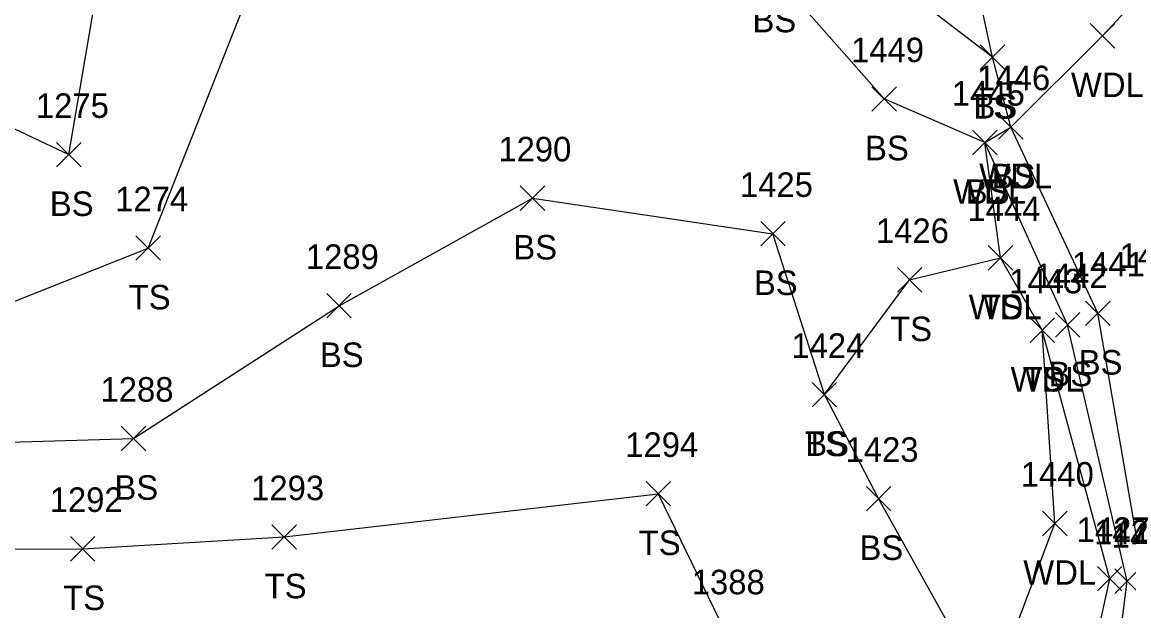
# Model space of a CAD drawing. Extents: x 1600281 to 1602254, y 862855 to 863227.
# Drawn here: x 1601927.2 to 1602017.5, y 862978.2 to 863026.2 of the extents above; entities that cross this region are included whole.
import ezdxf

# ---------------------------------------------------------------- set-up
doc = ezdxf.new("R2010")
doc.units = 0
for name, color, linetype in [('L_A', 7, 'Continuous'), ('L_I', 7, 'Continuous'), ('L_TIC', 7, 'Continuous'), ('LAWA', 7, 'Continuous'), ('LELB', 7, 'Continuous')]:
    doc.layers.add(name, color=color, linetype=linetype)

msp = doc.modelspace()

# ---------------------------------------------------------------- linework, layer by layer
at = {"layer": 'L_TIC'}
for points in [[(1602014.328, 863024.061), (1602016.328, 863026.061)], [(1602016.328, 863024.061), (1602014.328, 863026.061)], [(1602005.36, 863022.315), (1602007.36, 863024.315)], [(1602007.36, 863022.315), (1602005.36, 863024.315)], [(1602005.36, 863022.315), (1602007.36, 863024.315)], [(1602007.36, 863022.315), (1602005.36, 863024.315)], [(1601996.522, 863018.91), (1601998.522, 863020.91)], [(1601998.522, 863018.91), (1601996.522, 863020.91)], [(1602006.852, 863016.624), (1602008.852, 863018.624)], [(1602008.852, 863016.624), (1602006.852, 863018.624)], [(1602006.852, 863016.624), (1602008.852, 863018.624)], [(1602008.852, 863016.624), (1602006.852, 863018.624)], [(1602004.728, 863015.362), (1602006.728, 863017.362)], [(1602006.728, 863015.362), (1602004.728, 863017.362)], [(1602004.728, 863015.362), (1602006.728, 863017.362)], [(1602006.728, 863015.362), (1602004.728, 863017.362)], [(1601930.055, 863014.369), (1601932.055, 863016.369)], [(1601932.055, 863014.369), (1601930.055, 863016.369)], [(1601967.846, 863010.822), (1601969.846, 863012.822)], [(1601969.846, 863010.822), (1601967.846, 863012.822)], [(1601987.456, 863007.925), (1601989.456, 863009.925)], [(1601989.456, 863007.925), (1601987.456, 863009.925)], [(1601987.456, 863007.925), (1601989.456, 863009.925)], [(1601989.456, 863007.925), (1601987.456, 863009.925)], [(1601936.517, 863006.754), (1601938.517, 863008.754)], [(1601938.517, 863006.754), (1601936.517, 863008.754)], [(1602006, 863005.956), (1602008, 863007.956)], [(1602008, 863005.956), (1602006, 863007.956)], [(1602006, 863005.956), (1602008, 863007.956)], [(1602008, 863005.956), (1602006, 863007.956)], [(1601998.597, 863004.166), (1602000.597, 863006.166)], [(1602000.597, 863004.166), (1601998.597, 863006.166)], [(1601952.074, 863002.055), (1601954.074, 863004.055)], [(1601954.074, 863002.055), (1601952.074, 863004.055)], [(1602013.943, 863001.438), (1602015.943, 863003.438)], [(1602015.943, 863001.438), (1602013.943, 863003.438)], [(1602009.41, 863000.058), (1602011.41, 863002.058)], [(1602011.41, 863000.058), (1602009.41, 863002.058)], [(1602009.41, 863000.058), (1602011.41, 863002.058)], [(1602011.41, 863000.058), (1602009.41, 863002.058)], [(1602011.478, 863000.488), (1602013.478, 863002.488)], [(1602013.478, 863000.488), (1602011.478, 863002.488)], [(1601991.646, 862994.803), (1601993.646, 862996.803)], [(1601993.646, 862994.803), (1601991.646, 862996.803)], [(1601991.646, 862994.803), (1601993.646, 862996.803)], [(1601993.646, 862994.803), (1601991.646, 862996.803)], [(1601935.325, 862991.231), (1601937.325, 862993.231)], [(1601937.325, 862991.231), (1601935.325, 862993.231)], [(1601978.103, 862986.727), (1601980.103, 862988.727)], [(1601980.103, 862986.727), (1601978.103, 862988.727)], [(1601996.067, 862986.325), (1601998.067, 862988.325)], [(1601998.067, 862986.325), (1601996.067, 862988.325)], [(1602010.441, 862984.305), (1602012.441, 862986.305)], [(1602012.441, 862984.305), (1602010.441, 862986.305)], [(1601947.603, 862983.199), (1601949.603, 862985.199)], [(1601949.603, 862983.199), (1601947.603, 862985.199)], [(1601931.18, 862982.24), (1601933.18, 862984.24)], [(1601933.18, 862982.24), (1601931.18, 862984.24)], [(1602014.906, 862979.796), (1602016.906, 862981.796)], [(1602016.906, 862979.796), (1602014.906, 862981.796)], [(1602016.327, 862979.602), (1602018.327, 862981.602)], [(1602018.327, 862979.602), (1602016.327, 862981.602)]]:
    msp.add_lwpolyline(points, dxfattribs=at)
at = {"layer": 'LAWA'}
msp.add_lwpolyline([(1601918.484, 862969.325), (1601939.42, 862962.53), (1601955.985, 862947.407), (1601971.758, 862937.876), (1601975.725, 862943.556), (1601990.974, 862965.699), (1602006.102, 862971.122), (1602011.441, 862985.305), (1602010.41, 863001.058), (1602007, 863006.956), (1602005.728, 863016.362), (1602007.852, 863017.624), (1602015.328, 863025.061), (1602020.118, 863030.26)], dxfattribs=at)
at = {"layer": 'LELB'}
for points in [[(1601889.548, 862979.701), (1601879.53, 862980.196), (1601869.363, 862989.31), (1601873.745, 863000.271), (1601884.058, 863016.502), (1601890.014, 863028.231), (1601890.388, 863044.156), (1601893.555, 863052.296), (1601898.678, 863064.416), (1601898.005, 863054.108), (1601899.316, 863041.878), (1601901.962, 863029.12), (1601931.055, 863015.369), (1601935.902, 863043.881), (1601936.523, 863051.716)], [(1602006.36, 863023.315), (1601992.353, 863034.019), (1601989.377, 863048.159), (1601987.871, 863058.21)], [(1601850.487, 862982.969), (1601860.819, 862978.517), (1601879.357, 862968.779), (1601889.404, 862966.06), (1601913.787, 862945.707), (1601936.178, 862934.785), (1601958.999, 862928.536), (1601973.106, 862927.744), (1601983.044, 862929.485), (1601994.912, 862935.464), (1602008.175, 862945.227), (1602016.316, 862961.337), (1602018.761, 862980.317), (1602014.943, 863002.438), (1602007.852, 863017.624), (1602006.36, 863023.315), (1602003.161, 863037.99), (1602002.758, 863044.77), (1602006.602, 863051.128), (1602010.649, 863053.195)], [(1601881.596, 863023.768), (1601884.862, 863033.619), (1601890.388, 863044.156), (1601893.063, 863038.692), (1601893.536, 863030.212), (1601909.571, 863016.62), (1601907.502, 863002.961), (1601921.846, 863001.516), (1601937.517, 863007.754), (1601947.495, 863033.023)], [(1601958.999, 862928.536), (1601972.89, 862929.468), (1601981.162, 862933.435), (1601993.258, 862937.414), (1602005.114, 862948.359), (1602014.99, 862961.982), (1602017.327, 862980.602), (1602012.478, 863001.488), (1602005.728, 863016.362), (1601997.522, 863019.91), (1601988.341, 863030.346), (1601976.19, 863036.164)], [(1601913.251, 862991.536), (1601936.325, 862992.231), (1601953.074, 863003.055), (1601968.846, 863011.822), (1601988.456, 863008.925)], [(1602006.102, 862971.122), (1601997.067, 862987.325), (1601992.646, 862995.803), (1601988.456, 863008.925)], [(1601992.646, 862995.803), (1601999.597, 863005.166), (1602007, 863006.956)], [(1601991.981, 862939.355), (1602001.74, 862950.45), (1602012.079, 862963.37), (1602015.906, 862980.796), (1602010.41, 863001.058)], [(1601907.639, 862983.211), (1601932.18, 862983.24), (1601948.603, 862984.199), (1601979.103, 862987.727), (1601984.528, 862976.525), (1601990.974, 862965.699)]]:
    msp.add_lwpolyline(points, dxfattribs=at)

# ---------------------------------------------------------------- texts
at = {"layer": 'L_A'}
for s, p in [('BS', (1601986.782, 863025.346)), ('WDL', (1602012.745, 863020.061)), ('TS', (1602004.769, 863018.315)), ('BS', (1602004.801, 863018.315)), ('BS', (1601995.963, 863014.91)), ('WDL', (1602005.269, 863012.624)), ('BS', (1602006.293, 863012.624)), ('WDL', (1602003.145, 863011.362)), ('BS', (1602004.169, 863011.362)), ('BS', (1601929.496, 863010.369)), ('BS', (1601967.287, 863006.822)), ('BS', (1601986.897, 863003.925)), ('BS', (1601986.897, 863003.925)), ('TS', (1601935.927, 863002.754)), ('WDL', (1602004.417, 863001.956)), ('TS', (1602005.409, 863001.956)), ('TS', (1601998.007, 863000.166)), ('BS', (1601951.515, 862998.055)), ('BS', (1602013.384, 862997.438)), ('BS', (1602010.919, 862996.488)), ('WDL', (1602007.827, 862996.058)), ('TS', (1602008.819, 862996.058)), ('TS', (1601991.056, 862990.803)), ('BS', (1601991.087, 862990.803)), ('BS', (1601934.766, 862987.231)), ('TS', (1601977.512, 862982.727)), ('BS', (1601995.508, 862982.325)), ('WDL', (1602008.859, 862980.305)), ('TS', (1601947.013, 862979.199)), ('TS', (1601930.589, 862978.24))]:
    msp.add_text(s, height=2, dxfattribs=at).set_placement(p)
at = {"layer": 'L_I'}
for s, p in [('1449', (1601994.821, 863022.91)), ('1446', (1602005.104, 863020.624)), ('1446', (1602005.104, 863020.624)), ('1445', (1602003.035, 863019.362)), ('1445', (1602003.035, 863019.362)), ('1275', (1601928.363, 863018.369)), ('1290', (1601966.066, 863014.822)), ('1425', (1601985.763, 863011.925)), ('1425', (1601985.763, 863011.925)), ('1274', (1601934.824, 863010.754)), ('1444', (1602004.307, 863009.956)), ('1444', (1602004.307, 863009.956)), ('1426', (1601996.849, 863008.166)), ('1289', (1601950.373, 863006.055)), ('1441', (1602012.817, 863005.438)), ('1439', (1602016.704, 863006.133)), ('1442', (1602009.786, 863004.488)), ('1443', (1602007.717, 863004.058)), ('1443', (1602007.717, 863004.058)), ('1424', (1601989.953, 862998.803)), ('1424', (1601989.953, 862998.803)), ('1288', (1601933.632, 862995.231)), ('1294', (1601976.41, 862990.727)), ('1423', (1601994.374, 862990.325)), ('1440', (1602008.662, 862988.305)), ('1293', (1601945.91, 862987.199)), ('1292', (1601929.487, 862986.24)), ('1427', (1602013.213, 862983.796)), ('1428', (1602014.634, 862983.602)), ('1429', (1602016.06, 862983.317)), ('1388', (1601981.835, 862979.525))]:
    msp.add_text(s, height=2, dxfattribs=at).set_placement(p)

doc.saveas('drawing.dxf')
